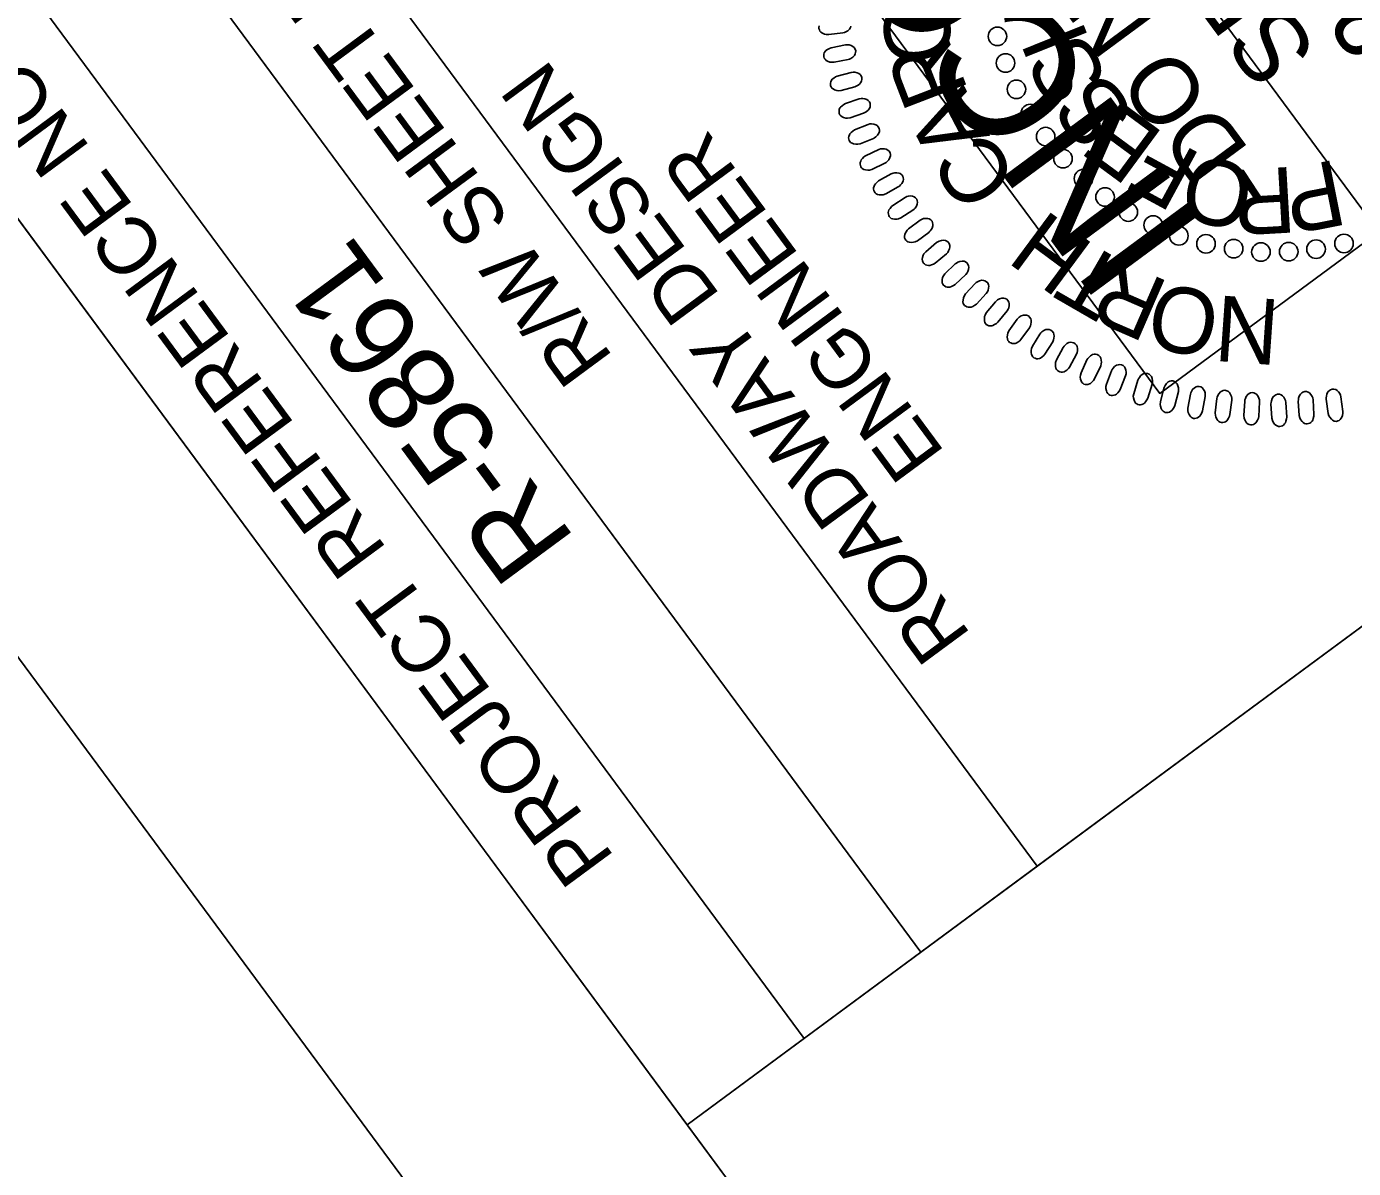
# Model space of a CAD drawing. Extents: x 474314 to 476195, y 501901 to 503905.
# Drawn here: x 474403.8 to 474518.3, y 503089.8 to 503188.4 of the extents above; entities that cross this region are included whole.
import ezdxf

# ---------------------------------------------------------------- set-up
doc = ezdxf.new("R2010")
doc.units = 0
for name, color, linetype in [('Sheet Clip Boundary CELL', 7, 'Continuous'), ('Sheet Data Field CELL', 7, 'Continuous'), ('Sheet PE Seal Cell', 7, 'Continuous'), ('Sheet Plan CELL', 7, 'Continuous'), ('Sheet Plot Border Outside CELL', 7, 'Continuous'), ('Sheet Sticker Incomplete CELL', 7, 'Continuous')]:
    doc.layers.add(name, color=color, linetype=linetype)

msp = doc.modelspace()

# ---------------------------------------------------------------- linework, layer by layer
at = {"layer": 'Sheet Clip Boundary CELL'}
msp.add_lwpolyline([(474600.43, 503196.68), (474460.82, 503093.56), (475070.85, 502267.56), (475070.85, 502267.56), (475070.85, 502267.56), (475070.85, 502267.56), (475070.85, 502267.56), (475070.85, 502267.56), (475422.16, 502337.99), (475422.16, 502337.99), (476046.45, 502713.99), (475412.07, 503572.99), (475380.25, 503549.49), (475256.12, 503717.56), (475223.58, 503693.53), (475026.19, 503617.59), (474539.96, 503278.51)], close=True, dxfattribs=at)
at = {"layer": 'Sheet PE Seal Cell'}
msp.add_lwpolyline([(474474.96, 503188.4), (474474.92, 503188.29), (474474.84, 503188.15), (474474.69, 503188.01), (474474.52, 503187.92), (474474.4, 503187.87), (474474.27, 503187.84), (474473.06, 503187.68), (474472.83, 503187.69), (474472.69, 503187.72), (474472.5, 503187.81), (474472.38, 503187.89), (474472.29, 503187.99), (474472.24, 503188.09), (474472.2, 503188.2), (474472.21, 503188.31), (474472.22, 503188.44)], dxfattribs=at)
for points in [[(474474.72, 503185.53), (474473.51, 503185.29), (474473.29, 503185.29), (474473.14, 503185.31), (474472.95, 503185.39), (474472.83, 503185.46), (474472.73, 503185.56), (474472.67, 503185.65), (474472.63, 503185.76), (474472.63, 503185.87), (474472.63, 503185.99), (474472.67, 503186.11), (474472.75, 503186.23), (474472.81, 503186.3), (474472.95, 503186.4), (474473.11, 503186.49), (474473.26, 503186.55), (474474.49, 503186.8), (474474.67, 503186.81), (474474.81, 503186.79), (474474.99, 503186.74), (474475.14, 503186.65), (474475.24, 503186.57), (474475.33, 503186.43), (474475.38, 503186.29), (474475.37, 503186.13), (474475.34, 503186.02), (474475.27, 503185.88), (474475.12, 503185.73), (474474.96, 503185.63), (474474.84, 503185.57)], [(474475.3, 503183.17), (474474.11, 503182.86), (474473.89, 503182.84), (474473.74, 503182.85), (474473.55, 503182.92), (474473.42, 503182.99), (474473.31, 503183.07), (474473.25, 503183.16), (474473.2, 503183.27), (474473.19, 503183.38), (474473.19, 503183.5), (474473.22, 503183.62), (474473.29, 503183.75), (474473.35, 503183.83), (474473.48, 503183.93), (474473.63, 503184.03), (474473.78, 503184.1), (474475, 503184.42), (474475.17, 503184.45), (474475.31, 503184.44), (474475.49, 503184.39), (474475.65, 503184.32), (474475.75, 503184.25), (474475.85, 503184.11), (474475.91, 503183.97), (474475.91, 503183.82), (474475.89, 503183.7), (474475.82, 503183.55), (474475.69, 503183.39), (474475.54, 503183.28), (474475.42, 503183.22)], [(474476.06, 503180.9), (474474.9, 503180.51), (474474.68, 503180.48), (474474.53, 503180.48), (474474.33, 503180.54), (474474.2, 503180.59), (474474.09, 503180.68), (474474.02, 503180.76), (474473.96, 503180.86), (474473.94, 503180.97), (474473.94, 503181.1), (474473.96, 503181.22), (474474.02, 503181.35), (474474.08, 503181.43), (474474.2, 503181.54), (474474.35, 503181.65), (474474.49, 503181.73), (474475.68, 503182.13), (474475.85, 503182.16), (474476, 503182.16), (474476.18, 503182.13), (474476.35, 503182.07), (474476.45, 503182), (474476.56, 503181.87), (474476.62, 503181.73), (474476.63, 503181.58), (474476.62, 503181.46), (474476.57, 503181.31), (474476.44, 503181.15), (474476.29, 503181.02), (474476.18, 503180.96)], [(474476.9, 503178.72), (474475.76, 503178.26), (474475.54, 503178.21), (474475.39, 503178.21), (474475.19, 503178.25), (474475.06, 503178.3), (474474.94, 503178.37), (474474.86, 503178.45), (474474.8, 503178.55), (474474.78, 503178.66), (474474.76, 503178.78), (474474.78, 503178.9), (474474.83, 503179.04), (474474.88, 503179.12), (474475, 503179.24), (474475.14, 503179.36), (474475.28, 503179.45), (474476.44, 503179.92), (474476.61, 503179.97), (474476.75, 503179.98), (474476.94, 503179.95), (474477.11, 503179.9), (474477.22, 503179.84), (474477.33, 503179.72), (474477.41, 503179.59), (474477.43, 503179.43), (474477.42, 503179.32), (474477.37, 503179.16), (474477.26, 503178.99), (474477.12, 503178.86), (474477.01, 503178.78)], [(474477.89, 503176.58), (474476.78, 503176.05), (474476.57, 503175.99), (474476.42, 503175.98), (474476.22, 503176.01), (474476.08, 503176.05), (474475.95, 503176.11), (474475.87, 503176.19), (474475.81, 503176.28), (474475.78, 503176.39), (474475.75, 503176.51), (474475.76, 503176.63), (474475.81, 503176.77), (474475.85, 503176.86), (474475.96, 503176.99), (474476.09, 503177.12), (474476.23, 503177.21), (474477.36, 503177.76), (474477.52, 503177.81), (474477.66, 503177.83), (474477.85, 503177.82), (474478.02, 503177.78), (474478.14, 503177.72), (474478.26, 503177.61), (474478.34, 503177.48), (474478.37, 503177.33), (474478.37, 503177.21), (474478.33, 503177.06), (474478.23, 503176.88), (474478.1, 503176.74), (474478, 503176.65)], [(474479.05, 503174.53), (474477.97, 503173.93), (474477.76, 503173.86), (474477.62, 503173.84), (474477.41, 503173.85), (474477.27, 503173.88), (474477.15, 503173.94), (474477.06, 503174.01), (474476.99, 503174.1), (474476.95, 503174.21), (474476.92, 503174.33), (474476.92, 503174.45), (474476.96, 503174.59), (474477, 503174.68), (474477.09, 503174.81), (474477.22, 503174.95), (474477.35, 503175.05), (474478.44, 503175.67), (474478.6, 503175.73), (474478.75, 503175.76), (474478.93, 503175.76), (474479.11, 503175.73), (474479.22, 503175.69), (474479.35, 503175.58), (474479.44, 503175.46), (474479.48, 503175.31), (474479.49, 503175.19), (474479.46, 503175.03), (474479.37, 503174.84), (474479.25, 503174.7), (474479.15, 503174.61)], [(474480.31, 503172.53), (474479.28, 503171.86), (474479.07, 503171.78), (474478.93, 503171.74), (474478.72, 503171.75), (474478.58, 503171.77), (474478.45, 503171.82), (474478.36, 503171.89), (474478.28, 503171.97), (474478.24, 503172.07), (474478.2, 503172.19), (474478.19, 503172.31), (474478.22, 503172.45), (474478.25, 503172.55), (474478.34, 503172.68), (474478.46, 503172.83), (474478.58, 503172.94), (474479.64, 503173.62), (474479.79, 503173.7), (474479.93, 503173.74), (474480.11, 503173.75), (474480.29, 503173.73), (474480.41, 503173.69), (474480.55, 503173.59), (474480.65, 503173.48), (474480.69, 503173.33), (474480.71, 503173.21), (474480.69, 503173.05), (474480.62, 503172.86), (474480.5, 503172.71), (474480.41, 503172.61)], [(474481.69, 503170.61), (474480.7, 503169.89), (474480.5, 503169.79), (474480.36, 503169.75), (474480.16, 503169.73), (474480.01, 503169.75), (474479.88, 503169.79), (474479.78, 503169.85), (474479.7, 503169.93), (474479.65, 503170.03), (474479.6, 503170.15), (474479.59, 503170.27), (474479.61, 503170.41), (474479.64, 503170.5), (474479.72, 503170.65), (474479.83, 503170.8), (474479.94, 503170.92), (474480.95, 503171.67), (474481.1, 503171.75), (474481.24, 503171.8), (474481.42, 503171.82), (474481.6, 503171.81), (474481.72, 503171.78), (474481.86, 503171.69), (474481.97, 503171.58), (474482.02, 503171.44), (474482.04, 503171.32), (474482.04, 503171.16), (474481.97, 503170.97), (474481.87, 503170.8), (474481.78, 503170.7)], [(474482.36, 503169.72), (474481.42, 503168.93), (474481.27, 503168.76), (474481.2, 503168.63), (474481.14, 503168.44), (474481.12, 503168.29), (474481.13, 503168.16), (474481.17, 503168.05), (474481.23, 503167.95), (474481.31, 503167.88), (474481.41, 503167.81), (474481.53, 503167.77), (474481.67, 503167.75), (474481.77, 503167.76), (474481.93, 503167.8), (474482.1, 503167.87), (474482.24, 503167.96), (474483.21, 503168.76), (474483.32, 503168.88), (474483.4, 503169.01), (474483.47, 503169.18), (474483.5, 503169.36), (474483.5, 503169.48), (474483.44, 503169.64), (474483.36, 503169.77), (474483.24, 503169.86), (474483.13, 503169.9), (474482.97, 503169.94), (474482.77, 503169.92), (474482.58, 503169.85), (474482.47, 503169.8)], [(474483.97, 503167.88), (474483.08, 503167.04), (474482.95, 503166.86), (474482.88, 503166.72), (474482.84, 503166.52), (474482.83, 503166.38), (474482.85, 503166.24), (474482.89, 503166.14), (474482.95, 503166.04), (474483.04, 503165.98), (474483.15, 503165.91), (474483.26, 503165.88), (474483.41, 503165.87), (474483.51, 503165.88), (474483.66, 503165.94), (474483.83, 503166.02), (474483.96, 503166.11), (474484.88, 503166.97), (474484.99, 503167.11), (474485.06, 503167.23), (474485.11, 503167.41), (474485.13, 503167.59), (474485.12, 503167.71), (474485.06, 503167.87), (474484.97, 503167.99), (474484.84, 503168.07), (474484.73, 503168.11), (474484.57, 503168.13), (474484.36, 503168.1), (474484.19, 503168.03), (474484.07, 503167.96)], [(474485.68, 503166.19), (474484.85, 503165.29), (474484.73, 503165.1), (474484.67, 503164.96), (474484.64, 503164.76), (474484.63, 503164.61), (474484.66, 503164.48), (474484.71, 503164.38), (474484.78, 503164.29), (474484.88, 503164.23), (474484.98, 503164.17), (474485.1, 503164.14), (474485.25, 503164.14), (474485.34, 503164.16), (474485.49, 503164.22), (474485.66, 503164.31), (474485.79, 503164.42), (474486.64, 503165.33), (474486.74, 503165.47), (474486.8, 503165.61), (474486.85, 503165.78), (474486.86, 503165.96), (474486.84, 503166.09), (474486.77, 503166.24), (474486.67, 503166.35), (474486.53, 503166.43), (474486.42, 503166.46), (474486.26, 503166.47), (474486.06, 503166.43), (474485.89, 503166.35), (474485.78, 503166.27)], [(474487.43, 503164.61), (474486.65, 503163.66), (474486.54, 503163.47), (474486.5, 503163.33), (474486.48, 503163.12), (474486.48, 503162.98), (474486.52, 503162.84), (474486.58, 503162.75), (474486.65, 503162.66), (474486.75, 503162.6), (474486.86, 503162.55), (474486.98, 503162.53), (474487.12, 503162.54), (474487.22, 503162.57), (474487.37, 503162.64), (474487.53, 503162.74), (474487.65, 503162.85), (474488.44, 503163.82), (474488.53, 503163.97), (474488.59, 503164.1), (474488.62, 503164.28), (474488.62, 503164.46), (474488.6, 503164.59), (474488.51, 503164.73), (474488.41, 503164.84), (474488.27, 503164.91), (474488.15, 503164.93), (474487.99, 503164.94), (474487.79, 503164.88), (474487.63, 503164.78), (474487.52, 503164.7)], [(474489.31, 503163.1), (474488.6, 503162.1), (474488.5, 503161.91), (474488.47, 503161.76), (474488.46, 503161.56), (474488.47, 503161.41), (474488.52, 503161.28), (474488.58, 503161.19), (474488.66, 503161.11), (474488.76, 503161.06), (474488.88, 503161.01), (474489, 503161), (474489.14, 503161.02), (474489.23, 503161.05), (474489.38, 503161.13), (474489.53, 503161.24), (474489.64, 503161.36), (474490.38, 503162.38), (474490.46, 503162.53), (474490.5, 503162.67), (474490.52, 503162.85), (474490.51, 503163.03), (474490.48, 503163.15), (474490.39, 503163.29), (474490.28, 503163.4), (474490.13, 503163.45), (474490.02, 503163.47), (474489.86, 503163.46), (474489.66, 503163.39), (474489.5, 503163.29), (474489.4, 503163.2)], [(474491.28, 503161.82), (474490.63, 503160.78), (474490.55, 503160.57), (474490.51, 503160.42), (474490.52, 503160.22), (474490.54, 503160.08), (474490.6, 503159.95), (474490.67, 503159.86), (474490.75, 503159.78), (474490.86, 503159.74), (474490.97, 503159.7), (474491.09, 503159.7), (474491.24, 503159.73), (474491.33, 503159.76), (474491.46, 503159.86), (474491.61, 503159.98), (474491.71, 503160.1), (474492.39, 503161.16), (474492.46, 503161.32), (474492.49, 503161.46), (474492.5, 503161.64), (474492.48, 503161.82), (474492.44, 503161.94), (474492.34, 503162.07), (474492.22, 503162.17), (474492.07, 503162.21), (474491.96, 503162.23), (474491.8, 503162.21), (474491.61, 503162.13), (474491.45, 503162.01), (474491.36, 503161.92)], [(474493.29, 503160.67), (474492.7, 503159.59), (474492.63, 503159.38), (474492.61, 503159.23), (474492.63, 503159.03), (474492.66, 503158.89), (474492.72, 503158.76), (474492.8, 503158.68), (474492.89, 503158.61), (474493, 503158.57), (474493.11, 503158.54), (474493.23, 503158.54), (474493.37, 503158.58), (474493.46, 503158.62), (474493.6, 503158.72), (474493.73, 503158.85), (474493.83, 503158.98), (474494.43, 503160.08), (474494.49, 503160.24), (474494.52, 503160.39), (474494.52, 503160.57), (474494.48, 503160.75), (474494.44, 503160.86), (474494.33, 503160.99), (474494.21, 503161.08), (474494.05, 503161.11), (474493.94, 503161.12), (474493.78, 503161.09), (474493.59, 503161), (474493.45, 503160.88), (474493.36, 503160.78)], [(474495.34, 503159.6), (474494.83, 503158.48), (474494.77, 503158.27), (474494.76, 503158.12), (474494.79, 503157.92), (474494.83, 503157.78), (474494.9, 503157.66), (474494.98, 503157.58), (474495.07, 503157.51), (474495.18, 503157.48), (474495.3, 503157.46), (474495.42, 503157.47), (474495.56, 503157.52), (474495.65, 503157.56), (474495.77, 503157.67), (474495.9, 503157.81), (474495.99, 503157.95), (474496.52, 503159.08), (474496.57, 503159.25), (474496.59, 503159.39), (474496.57, 503159.57), (474496.53, 503159.75), (474496.48, 503159.86), (474496.36, 503159.98), (474496.23, 503160.06), (474496.08, 503160.09), (474495.96, 503160.09), (474495.81, 503160.05), (474495.63, 503159.95), (474495.49, 503159.81), (474495.41, 503159.71)], [(474497.46, 503158.65), (474497.01, 503157.51), (474496.97, 503157.29), (474496.97, 503157.14), (474497.01, 503156.94), (474497.06, 503156.8), (474497.14, 503156.69), (474497.22, 503156.61), (474497.32, 503156.55), (474497.43, 503156.53), (474497.55, 503156.52), (474497.67, 503156.54), (474497.81, 503156.59), (474497.89, 503156.64), (474498.01, 503156.76), (474498.13, 503156.9), (474498.21, 503157.05), (474498.67, 503158.21), (474498.71, 503158.38), (474498.72, 503158.53), (474498.69, 503158.71), (474498.64, 503158.88), (474498.57, 503158.99), (474498.45, 503159.1), (474498.32, 503159.17), (474498.16, 503159.19), (474498.05, 503159.18), (474497.89, 503159.13), (474497.72, 503159.02), (474497.59, 503158.88), (474497.52, 503158.77)], [(474499.74, 503157.85), (474499.37, 503156.68), (474499.33, 503156.46), (474499.34, 503156.31), (474499.4, 503156.11), (474499.46, 503155.98), (474499.54, 503155.87), (474499.63, 503155.8), (474499.73, 503155.75), (474499.84, 503155.73), (474499.96, 503155.72), (474500.08, 503155.75), (474500.21, 503155.81), (474500.29, 503155.87), (474500.4, 503155.99), (474500.51, 503156.15), (474500.58, 503156.29), (474500.97, 503157.49), (474501, 503157.65), (474501, 503157.8), (474500.96, 503157.98), (474500.9, 503158.15), (474500.83, 503158.25), (474500.7, 503158.36), (474500.56, 503158.42), (474500.41, 503158.43), (474500.29, 503158.41), (474500.14, 503158.36), (474499.97, 503158.23), (474499.86, 503158.08), (474499.79, 503157.96)], [(474501.97, 503157.16), (474501.67, 503155.97), (474501.66, 503155.75), (474501.67, 503155.6), (474501.74, 503155.41), (474501.81, 503155.28), (474501.9, 503155.17), (474501.99, 503155.11), (474502.1, 503155.06), (474502.21, 503155.05), (474502.33, 503155.05), (474502.45, 503155.09), (474502.57, 503155.16), (474502.65, 503155.22), (474502.75, 503155.35), (474502.85, 503155.51), (474502.91, 503155.66), (474503.23, 503156.88), (474503.24, 503157.05), (474503.23, 503157.19), (474503.19, 503157.37), (474503.11, 503157.53), (474503.04, 503157.63), (474502.9, 503157.73), (474502.76, 503157.78), (474502.6, 503157.78), (474502.49, 503157.76), (474502.34, 503157.69), (474502.19, 503157.56), (474502.08, 503157.4), (474502.02, 503157.28)], [(474504.27, 503156.63), (474504.05, 503155.43), (474504.05, 503155.21), (474504.07, 503155.06), (474504.15, 503154.87), (474504.23, 503154.75), (474504.32, 503154.65), (474504.42, 503154.59), (474504.53, 503154.55), (474504.64, 503154.55), (474504.76, 503154.56), (474504.88, 503154.6), (474505, 503154.68), (474505.07, 503154.74), (474505.16, 503154.88), (474505.26, 503155.04), (474505.31, 503155.2), (474505.54, 503156.43), (474505.55, 503156.6), (474505.53, 503156.75), (474505.47, 503156.92), (474505.38, 503157.08), (474505.3, 503157.18), (474505.16, 503157.26), (474505.02, 503157.31), (474504.86, 503157.3), (474504.75, 503157.27), (474504.61, 503157.19), (474504.46, 503157.05), (474504.36, 503156.88), (474504.31, 503156.76)], [(474506.55, 503156.25), (474506.41, 503155.04), (474506.42, 503154.81), (474506.45, 503154.67), (474506.55, 503154.49), (474506.63, 503154.37), (474506.73, 503154.27), (474506.83, 503154.22), (474506.94, 503154.19), (474507.05, 503154.2), (474507.18, 503154.21), (474507.29, 503154.26), (474507.4, 503154.34), (474507.47, 503154.42), (474507.56, 503154.56), (474507.64, 503154.73), (474507.68, 503154.88), (474507.83, 503156.13), (474507.83, 503156.3), (474507.8, 503156.45), (474507.73, 503156.62), (474507.64, 503156.77), (474507.55, 503156.86), (474507.4, 503156.94), (474507.25, 503156.97), (474507.1, 503156.95), (474506.99, 503156.91), (474506.85, 503156.83), (474506.72, 503156.68), (474506.63, 503156.51), (474506.58, 503156.38)], [(474508.95, 503156.02), (474508.88, 503154.79), (474508.91, 503154.57), (474508.95, 503154.43), (474509.05, 503154.25), (474509.14, 503154.14), (474509.25, 503154.05), (474509.35, 503154.01), (474509.46, 503153.98), (474509.58, 503153.99), (474509.7, 503154.02), (474509.81, 503154.07), (474509.92, 503154.17), (474509.98, 503154.24), (474510.06, 503154.39), (474510.13, 503154.56), (474510.16, 503154.72), (474510.23, 503155.98), (474510.22, 503156.15), (474510.18, 503156.29), (474510.1, 503156.45), (474510, 503156.6), (474509.91, 503156.68), (474509.75, 503156.75), (474509.6, 503156.78), (474509.45, 503156.75), (474509.35, 503156.7), (474509.21, 503156.61), (474509.08, 503156.45), (474509.01, 503156.27), (474508.97, 503156.15)], [(474511.22, 503155.8), (474511.3, 503154.58), (474511.35, 503154.36), (474511.41, 503154.23), (474511.53, 503154.06), (474511.64, 503153.96), (474511.75, 503153.89), (474511.86, 503153.85), (474511.97, 503153.84), (474512.09, 503153.87), (474512.2, 503153.91), (474512.3, 503153.97), (474512.4, 503154.08), (474512.46, 503154.16), (474512.51, 503154.31), (474512.56, 503154.5), (474512.58, 503154.66), (474512.5, 503155.91), (474512.47, 503156.08), (474512.42, 503156.22), (474512.32, 503156.37), (474512.2, 503156.5), (474512.1, 503156.58), (474511.94, 503156.63), (474511.79, 503156.64), (474511.64, 503156.59), (474511.54, 503156.53), (474511.42, 503156.42), (474511.31, 503156.25), (474511.25, 503156.06), (474511.23, 503155.93)], [(474513.57, 503156.03), (474513.66, 503154.8), (474513.71, 503154.59), (474513.77, 503154.45), (474513.9, 503154.29), (474514, 503154.19), (474514.12, 503154.12), (474514.23, 503154.08), (474514.34, 503154.07), (474514.45, 503154.1), (474514.57, 503154.14), (474514.67, 503154.2), (474514.76, 503154.31), (474514.82, 503154.4), (474514.87, 503154.55), (474514.92, 503154.73), (474514.93, 503154.89), (474514.85, 503156.15), (474514.82, 503156.31), (474514.76, 503156.45), (474514.66, 503156.6), (474514.54, 503156.74), (474514.44, 503156.81), (474514.28, 503156.86), (474514.13, 503156.87), (474513.98, 503156.82), (474513.88, 503156.76), (474513.76, 503156.65), (474513.65, 503156.47), (474513.6, 503156.29), (474513.58, 503156.16)], [(474515.99, 503156.2), (474516.16, 503154.98), (474516.22, 503154.77), (474516.29, 503154.64), (474516.43, 503154.48), (474516.54, 503154.39), (474516.66, 503154.32), (474516.77, 503154.3), (474516.88, 503154.29), (474516.99, 503154.33), (474517.11, 503154.37), (474517.2, 503154.45), (474517.29, 503154.56), (474517.34, 503154.65), (474517.39, 503154.8), (474517.42, 503154.99), (474517.42, 503155.15), (474517.26, 503156.4), (474517.22, 503156.56), (474517.16, 503156.69), (474517.05, 503156.84), (474516.92, 503156.96), (474516.81, 503157.03), (474516.65, 503157.07), (474516.5, 503157.07), (474516.35, 503157.01), (474516.26, 503156.95), (474516.14, 503156.83), (474516.05, 503156.65), (474516, 503156.46), (474515.99, 503156.33)]]:
    msp.add_lwpolyline(points, close=True, dxfattribs=at)
for centre in [(474487.61, 503187.53), (474488.31, 503185.23), (474489.25, 503182.96), (474490.45, 503180.87), (474491.77, 503178.88), (474493.27, 503176.97), (474495.04, 503175.25), (474496.9, 503173.66), (474498.9, 503172.36), (474501.05, 503171.24), (474503.27, 503170.31), (474505.61, 503169.62), (474517.52, 503169.65), (474508, 503169.2), (474510.35, 503168.91), (474512.75, 503168.94), (474515.11, 503169.16)]:
    msp.add_circle(centre, 0.801, dxfattribs=at)
at = {"layer": 'Sheet Plan CELL'}
for p, q in [((474481, 503108.47), (474362.14, 503269.36)), ((474481, 503108.47), (474362.14, 503269.36)), ((474470.92, 503101.01), (474352.09, 503261.94)), ((474481, 503108.47), (474491.05, 503115.88))]:
    msp.add_line(p, q, dxfattribs=at)
for points in [[(474341.97, 503254.51), (475233.1, 502047.86), (476077.73, 502671.64), (475186.62, 503878.27)], [(474460.82, 503093.56), (474341.97, 503254.51), (474362.14, 503269.36), (474481, 503108.47)], [(474491.05, 503115.88), (474431.61, 503196.37), (474522.12, 503263.21), (474581.52, 503182.72)]]:
    msp.add_lwpolyline(points, close=True, dxfattribs=at)
at = {"layer": 'Sheet Plot Border Outside CELL'}
msp.add_lwpolyline([(476194.75, 502551.08), (475194.63, 503905.31), (474313.8, 503254.81), (475313.91, 501900.58)], close=True, dxfattribs=at)
at = {"layer": 'Sheet Sticker Incomplete CELL'}
msp.add_lwpolyline([(474520.52, 503170.66), (474501.62, 503156.7), (474414.29, 503274.95), (474433.19, 503288.91)], close=True, dxfattribs=at)

# ---------------------------------------------------------------- texts
at = {"layer": 'Sheet Data Field CELL'}
msp.add_text('R-5861', height=7.5, rotation=126.4463, dxfattribs=at).set_placement((474451.29, 503144.04))
at = {"layer": 'Sheet PE Seal Cell'}
for s, height, rotation, p in [('29470', 6.236, 126.4277, (474523.65, 503188.65)), ('SEAL', 6.236, 126.4277, (474515.39, 503186.24)), ('O', 5.67, 98.0766, (474483.9, 503185.57)), ('R', 5.67, 111.0553, (474485.13, 503182.8)), ('I', 5.67, 111.8558, (474495.58, 503187.21)), ('S', 5.67, 119.7956, (474497.33, 503183.77)), ('A', 5.67, 117.5447, (474486.99, 503178.94)), ('S', 5.67, 127.7354, (474499.7, 503180.73)), ('E', 5.67, 143.615, (474502.12, 503179.07)), ('C', 5.67, 124.034, (474489.54, 503175.14)), ('F', 5.67, 151.5548, (474505.37, 503177.26)), ('O', 5.67, 167.4344, (474510.09, 503176.15)), ('R', 5.67, 183.314, (474513.16, 503176.28)), ('P', 5.67, 191.2538, (474516.86, 503176.92)), ('H', 5.67, 143.5021, (474496.11, 503169.42)), ('T', 5.67, 149.9914, (474499.13, 503167.7)), ('R', 5.67, 156.4808, (474502.59, 503166.25)), ('O', 5.67, 169.4595, (474507.09, 503165.25)), ('N', 5.67, 175.9489, (474512.1, 503164.79))]:
    msp.add_text(s, height=height, rotation=rotation, dxfattribs=at).set_placement(p)
at = {"layer": 'Sheet Plan CELL'}
for s, height, p in [('R/W SHEET NO.', 5.0001, (474454.53, 503159.78)), ('PROJECT REFERENCE NO.', 5.0001, (474454.65, 503116.6)), ('ROADWAY DESIGN', 5.0001, (474485.41, 503135.81)), ('ENGINEER', 5, (474483.16, 503151.54))]:
    msp.add_text(s, height=height, rotation=126.4463, dxfattribs=at).set_placement(p)
at = {"layer": 'Sheet Sticker Incomplete CELL'}
for s, height, p in [('INCOMPLETE PLANS', 11.52, (474505.79, 503170.91)), ('DO NOT USE FOR R/W ACQUISITION', 5.76, (474509.45, 503177.65))]:
    msp.add_text(s, height=height, rotation=126.4463, dxfattribs=at).set_placement(p)

doc.saveas('drawing.dxf')
